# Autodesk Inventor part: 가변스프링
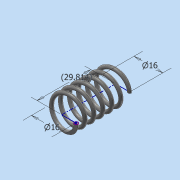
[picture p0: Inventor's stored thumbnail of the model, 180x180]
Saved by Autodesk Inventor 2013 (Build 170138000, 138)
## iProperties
Created: 2018-07
Part Number: 가변스프링
Material: 스테인리스강
Document SubType Name: Modeling
Designer: dgall
Density: 8.08 g/cm^3
Mass: 7.56055 g
Surface Area: 18.9234 cm^2
Volume: 0.935712 cm^3
Author: dgall
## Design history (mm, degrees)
sketch "스케치1"
  geometry: L1 (0, 0)-(0, 29.814); L2 (0, 29.814)-(8, 29.814); L3 (0, 0)-(8, 0); C1 r 1 at (8, 0)
  constraints: 6 end point, 1 centre point, 1 coincident, 1 parallel, 1 perpendicular, 1 vertical
  dimensions: "d0" = 29.81359 distance of L1.start L1.end (derived); "d1" = 16 diameter of L2.end L1; "d2" = 16 diameter of L3.end L1
feature "코일1" pitch "d3" = 10; turns "d5" = 6; dims "d4" = 29.81359 (= d0), "d6" = 0, angle "d7" = 90 deg, angle "d8" = 90 deg, "d9" = 0, "d10" = 0
node "작업 평면1"
feature "분할1"
feature "분할2"
node "솔리드1"
